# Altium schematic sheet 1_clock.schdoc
size 289 x 200 mm; Name: default297x210; Symbol: default297x210; Device: default297x210; Size: "A4"; Id: /; File: clock; Sheet: /; @Page No: 1; @Page Count: 1; @Schematic Name: clock; @Project Name: clock1_8; @Board Name: clock; @Update Date: 2025-09-24; @Create Time: 18:37:43; @Update Time: 20:37:44; @Page Name: clock; @Create Date: 2025-09-24
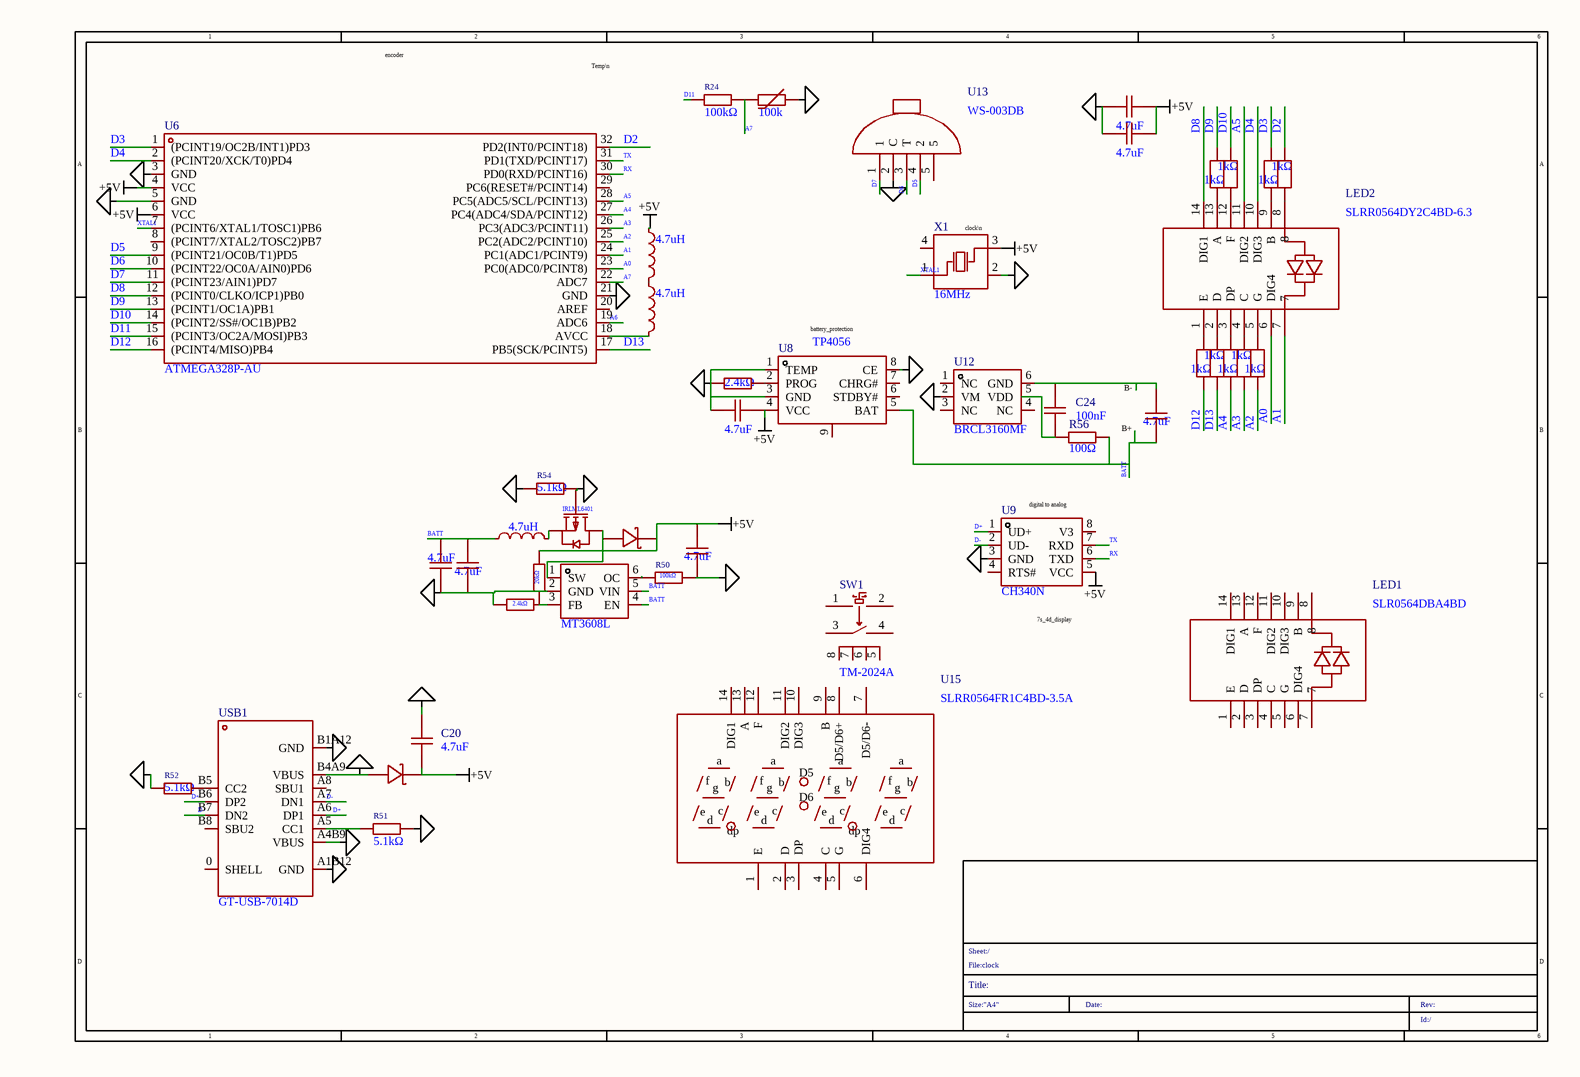
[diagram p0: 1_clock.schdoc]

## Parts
C15  4.7uF  [C0402]
C16  4.7uF  [C0402]
C19  4.7uF  [C0402]
C20  4.7uF  [C0402]
C21  4.7uF  [C0402]
C24  100nF  [C0402]
C25  4.7uF  [C0402]
C27  4.7uF  [C0402]
C28  4.7uF  [C0402]
D5  DSK34  [SOD-123_L2.8-W1.8-LS3.7-RD]  (value not drawn)
D6  DSK34  [SOD-123_L2.8-W1.8-LS3.7-RD]  (value not drawn)
L3  4.7uH  [L1206]
L5  4.7uH  [L1206]
L6  4.7uH  [L1206]
LED1  SLR0564DBA4BD  [LED-SEG-TH_SLR0564DBA4BD]
LED2  SLRR0564DY2C4BD-6.3  [LED-SEG-TH_SLRR0564DY2C4BD-6.3]
Q1  IRLML6401  [SOT-23-3_L2.9-W1.3-P1.90-LS2.4-BR]
R22  100k  [R0201]
R24  100kΩ  [R0402]
R39  1kΩ  [R0603]
R40  1kΩ  [R0603]
R41  1kΩ  [R0603]
R42  1kΩ  [R0603]
R43  1kΩ  [R0603]
R44  1kΩ  [R0603]
R45  1kΩ  [R0603]
R46  1kΩ  [R0603]
R48  2.4kΩ  [R0402]
R49  2.4kΩ  [R0402]
R50  100kΩ  [R0402]
R51  5.1kΩ  [R0402]
R52  5.1kΩ  [R0402]
R53  20kΩ  [R0402]
R54  5.1kΩ  [R0402]
R56  100Ω  [R0402]
R57  1kΩ  [R0603]
SW1  TM-2024A  [SW-SMD_TM-2024A]
U6  ATMEGA328P-AU  [TQFP-32_L7.0-W7.0-P0.80-LS9.0-BL]
U8  TP4056  [ESOP-8_L4.9-W3.9-P1.27-LS6.0-BL-EP-1]
U9  CH340N  [SOP-8_L4.9-W3.9-P1.27-LS6.0-BL]
U10  MT3608L  [SOT-23-6_L2.9-W1.6-P0.95-LS2.8-BL_3]
U12  BRCL3160MF  [SOT-23-6_L2.9-W1.6-P0.95-LS2.8-BL]
U13  WS-003DB  [SW-SMD_WS-003DB]
U15  SLRR0564FR1C4BD-3.5A  [LED-SEG-TH_14P-L50.2-W19.0-P2.54-S15.24-BL]
USB1  GT-USB-7014D  [USB-C-SMD_GT-USB-7014D]
X1  16MHz  [CRYSTAL-SMD_4P-L3.2-W2.5-BL]

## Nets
+5V: C19.2 C20.2 C21.1 C25.2 C27.2 D5.1(K) D6.1(K) L6.1 R53.2 U6.4(VCC) U6.6(VCC) U8.4(VCC) U9.5(VCC) X1.3(OSC2)
POWER_GND: C15.2 C16.2 C19.1 C20.1 C21.2 C25.1 C27.1 R22.2 R48.2 R49.2 R50.2 R51.1 R52.1 R54.1 U6.3(GND) U6.5(GND) U6.21(GND) U8.1(TEMP) U8.3(GND) U9.3(GND) U10.2(GND) U12.2(VM) U13.2(C) USB1.A1B12(GND) USB1.B1A12(GND) X1.2(GND)
POWER_VBUS: D6.2(A) Q1.1(G) R54.2 U8.8(CE) USB1.A4B9(VBUS) USB1.B4A9(VBUS)
A0: LED2.6(DIG4) U6.23(PC0(ADC0/PCINT8))
A1: LED2.7 U6.24(PC1(ADC1/PCINT9))
A2: R42.1 U6.25(PC2(ADC2/PCINT10))
A3: R43.1 U6.26(PC3(ADC3/PCINT11))
A4: R57.1 U6.27(PC4(ADC4/SDA/PCINT12))
A5: LED2.11(DIG2) U6.28(PC5(ADC5/SCL/PCINT13))
A6: U6.19(ADC6)
A7: R22.1 R24.2 U6.22(ADC7)
BATT: C15.1 C16.1 C28.2 L3.1 R56.2 U8.5(BAT) U10.4(EN) U10.5(VIN)
D2: R44.2 U6.32(PD2(INT0/PCINT18))
D3: R40.2 U6.1((PCINT19/OC2B/INT1)PD3)
D4: LED2.10(DIG3) U6.2((PCINT20/XCK/T0)PD4)
D5: U6.9((PCINT21/OC0B/T1)PD5) U13.4(2)
D6: U6.10((PCINT22/OC0A/AIN0)PD6) U13.3(T)
D7: U6.11((PCINT23/AIN1)PD7) U13.1
D8: LED2.14(DIG1) U6.12((PCINT0/CLKO/ICP1)PB0)
D9: R39.2 U6.13((PCINT1/OC1A)PB1)
D10: R41.2 U6.14((PCINT2/SS#/OC1B)PB2)
D11: R24.1 U6.15((PCINT3/OC2A/MOSI)PB3)
D12: R46.1 U6.16((PCINT4/MISO)PB4)
D13: R45.1 U6.17(PB5(SCK/PCINT5))
D+: U9.1(UD+) USB1.A6(DP1) USB1.B6(DP2)
D-: U9.2(UD-) USB1.A7(DN1) USB1.B7(DN2)
RX: U6.30(PD0(RXD/PCINT16)) U9.6(TXD)
TX: U6.31(PD1(TXD/PCINT17)) U9.7(RXD)
XTAL1: U6.7((PCINT6/XTAL1/TOSC1)PB6) X1.1(OSC1)
NetC24_1: C24.1 R56.1 U12.5(VDD)
NetC24_2: C24.2 C28.1 U12.6(GND)
NetD5_2: D5.2(A) Q1.3(D) U10.1(SW)
NetL3_2: L3.2 Q1.2(S)
NetL5_1: L5.1 L6.2
NetL5_2: L5.2 U6.18(AVCC)
NetLED2_1: LED2.1(E) R46.2
NetLED2_2: LED2.2(D) R45.2
NetLED2_3: LED2.3(DP) R57.2
NetLED2_4: LED2.4(C) R43.2
NetLED2_5: LED2.5(G) R42.2
NetLED2_8: LED2.8 R44.1
NetLED2_9: LED2.9(B) R40.1
NetLED2_12: LED2.12(F) R41.1
NetLED2_13: LED2.13(A) R39.1
NetR48_1: R48.1 U8.2(PROG)
NetR49_1: R49.1 R53.1 U10.3(FB)
NetR50_1: R50.1 U10.6(OC)
NetR51_2: R51.2 USB1.A5(CC1)
NetR52_2: R52.2 USB1.B5(CC2)

Not connected (* = marked no-connect by the designer): LED1 1(E) 2(D) 3(DP) 4(C) 5(G) 6(DIG4) 7 8 9(B) 10(DIG3) 11(DIG2) 12(F) 13(A) 14(DIG1); SW1 1 2 3 4 5 6 7 8; U6 8((PCINT7/XTAL2/TOSC2)PB7) 20(AREF) 29(PC6(RESET#/PCINT14)); U8 6(STDBY#) 7(CHRG#) 9(GND); U9 4(RTS#) 8(V3); U12 1(NC) 3(NC) 4(NC); U13 5; U15 1(E) 2(D) 3(DP) 4(C) 5(G) 6(DIG4) 7(D5/D6-) 8(D5/D6+) 9(B) 10(DIG3) 11(DIG2) 12(F) 13(A) 14(DIG1); USB1 0(SHELL) A8(SBU1) B8(SBU2); X1 4(GND)

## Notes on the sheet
- encoder
- Temp\n
- (near X1) clock\n
- (near U8) battery_protection
- (near C28) B-
- B+
- (near U9) digital to analog
- (near U9) 7s_4d_display

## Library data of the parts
C15 C16 C19-C21 C25 C27 C28 = CL05A475MQ5NRNC_C307423: Manufacturer: SAMSUNG(三星); Add into BOM: yes; Tolerance: ±20%; Voltage Rating: 6.3V; Temperature Coefficient: X5R
C24 = FCC0402B104K160AT: Manufacturer: FOJAN(富捷); Add into BOM: yes; Tolerance: ±10%; Voltage Rating: 16V; Temperature Coefficient: X7R
D5 D6 = DSK34_C41029: Manufacturer: MDD(辰达半导体); Add into BOM: yes; Diode Configuration: Independent; Voltage - Forward(Vf@If): 550mV@3A; Voltage - DC Reverse(Vr): 40V; Current - Rectified: 3A; Reverse Leakage Current (Ir): 500uA@40V; Operating Junction Temperature Range: -55℃~+150℃; Non-Repetitive Peak Forward Surge Current: 80A
L3 L5 L6 = CMI321609U4R7KT: Manufacturer: FH(风华); Add into BOM: yes; Tolerance: ±10%; Q @ Freq: 35@10MHz
LED1 = SLR0564DBA4BD: Manufacturer: SUNLIGHT(光华); Add into BOM: yes; Number of Characters: 4; Digit/Alpha Size(inch): 0.56; Illumination Color: Blue; LED Polarity: Common Anode
LED2 = SLRR0564DY2C4BD-6.3: Manufacturer: SUNLIGHT(光华); Add into BOM: yes; Number of Characters: 4Bit; Luminous Color: Yellow; LED Polarity: 共阴极; Digit/Alpha Size(inch): 0.56
Q1 = IRLML6401_C5190144: Manufacturer: Hottech(合科泰); Add into BOM: yes; Number: 1 P-Channel; Drain to Source Voltage: 30V; Current - Continuous Drain(Id): 4A; RDS(on): 52mΩ@10V,4A; Pd - Power Dissipation: 1.4W; Gate Threshold Voltage (Vgs(th)): 1.2V; Input Capacitance(Ciss): 645pF; Reverse Transfer Capacitance (Crss@Vds): 55pF
R22 = NCP03WF104F05RL: Manufacturer: muRata(村田); Add into BOM: yes; B Constant (25℃/85℃): 4311K; B Constant (25℃/100℃): 4334K; Steady State Current (Max): 100uA
R24 R50 = 0402WGF1003TCE: Manufacturer: UNI-ROYAL(厚声); Add into BOM: yes; Tolerance: ±1%; Power(Watts): 62.5mW; Voltage-Supply(Max): 50V; Temperature Coefficient: ±100ppm/℃
R39-R46 R57 = FRC0603F1001TS: Manufacturer: FOJAN(富捷); Add into BOM: yes; Tolerance: ±1%; Power(Watts): 100mW; Voltage-Supply(Max): 75V; Temperature Coefficient: ±100ppm/℃
R48 R49 = 0402WGF2401TCE: Manufacturer: UNI-ROYAL(厚声); Add into BOM: yes; Tolerance: ±1%; Temperature Coefficient: ±100ppm/℃
R51 R52 R54 = 0402WGF5101TCE: Manufacturer: UNI-ROYAL(厚声); Add into BOM: yes; Tolerance: ±1%; Power(Watts): 62.5mW; Voltage-Supply(Max): 50V; Temperature Coefficient: ±100ppm/℃
R53 = 0402WGF2002TCE: Manufacturer: UNI-ROYAL(厚声); Add into BOM: yes; Tolerance: ±1%; Temperature Coefficient: ±100ppm/℃
R56 = 0402WGF1000TCE: Manufacturer: UNI-ROYAL(厚声); Add into BOM: yes; Tolerance: ±1%; Temperature Coefficient: ±200ppm/℃
SW1 = TM-2024A: Manufacturer: XKB Connection(中国星坤); Add into BOM: yes
U6 = ATMEGA328P-AU_C14877: Manufacturer: MICROCHIP(美国微芯); Add into BOM: yes; CPU Core: AVR; CPU Maximum Speed: 20MHz; Program Storage Size: 32KB; Program Memory Type: FLASH; EEPROM: 1KB; Number of I/O: 23; ADC (Bit): 10bit; Voltage - Supply: 1.8V~5.5V
U8 = TP4056_C42422118: Manufacturer: TDSEMIC(拓电半导体); Add into BOM: yes; The Chip Type: Charging IC; Voltage - Supply: 4.5V~6V; Charge Current - Max: 1A; Charging Saturation Voltage: 4.2V; Type of Battery: Lithium Battery; Number of Cells: 1; Battery Temperature Detection: Support; Supply Current (Iq): 55uA
U9 = CH340N: Manufacturer: WCH(南京沁恒); Symbol: CH340N_C2977777; Add into BOM: yes; Applications Function: USB to serial; Number of Channels: 1; Voltage - Supply: 3.3V；5V; Data Rate: 2Mbps
U10 = MT3608L: Manufacturer: 西安航天民芯; Add into BOM: yes; Function: Boost; Voltage - Supply: 2.2V~16V; Output Current: 2.5A; Frequency - Switching: 1.2MHz; Synchronous Rectifier: No; Number of Outputs: 1; Quiescent Current: 100uA; Switch tube (built-in/external): Built-In; Output Type: Adjustable
U12 = BRCL3160MF: Manufacturer: BLUE ROCKET(蓝箭); Add into BOM: yes; The Chip Type: Protection IC; Voltage - Supply: 2.8V~6V; Charging Saturation Voltage: 4.35V; End-Off Voltage: 2.3V; Type of Battery: Lithium Battery; Number of Cells: 1; Battery Temperature Detection: Not Supported
U13 = WS-003DB: Manufacturer: HANBO(汉博); Add into BOM: yes
U15 = SLRR0564FR1C4BD-3.5A: Manufacturer: SUNLIGHT(光华); Add into BOM: yes; Number of Characters: 4; Digit/Alpha Size(inch): 0.56; Illumination Color: Red; LED Polarity: Common Cathode
USB1 = GT-USB-7014D: Manufacturer: G-Switch(品赞); Add into BOM: yes; Connector Type: Type-C; Protocol Standard: USB 2.0; Gender: Female; Number of Contacts: 16P; Number of Ports: 1; Current Rating-Power: 5A; Voltage Rating: 24V; Connect-Disconnect Life: 10,000 Cycles; Center Height: 0.52mm; Detection color: Black
X1 = TAXM16M4RLBCCT2T: Manufacturer: YJX(雅晶鑫); Symbol: SMD-3225_4P 16MHz 20pF 10ppm -40~+85℃; Add into BOM: yes; Normal temperature Frequency Tolerance: ±10ppm; Load Capacitance: 20pF; Frequency Stability: ±15ppm; Equivalent Series Resistance(ESR): 40Ω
